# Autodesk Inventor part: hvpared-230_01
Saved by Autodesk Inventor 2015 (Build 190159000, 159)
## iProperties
Created: 2020-08
Part Number: hvpared-230_01
Checked By: TraceParts S.A.
Material: Generic
Catalog Web Link: www.traceparts.com
Document SubType Name: Modeling
Designer: TraceParts
Density: 1 g/cm^3
Appearance: Default
Company: TraceParts S.A.
Author: TraceParts
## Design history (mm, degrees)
feature "hvpared-230_01.ipt"
body "Solid1"
